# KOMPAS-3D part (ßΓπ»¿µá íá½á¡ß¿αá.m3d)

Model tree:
1. Эскиз:1
2. Операция выдавливания:1
     Расстояние 1 = 12
3. Эскиз:2
4. Вырезать элемент выдавливания:1
     Расстояние 1 = 4
5. Эскиз:3
6. Отверстие:1
7. Эскиз:4
8. Отверстие:2
9. Эскиз:5
10. Вырезать элемент выдавливания:2
     Расстояние 1 = 1
11. Скругление:1
     Радиус = 0.1
12. Скругление:2
     Радиус = 0.1
13. Скругление:3
     Радиус = 0.1
14. Скругление:4
     Радиус = 1
15. Скругление:5
     Радиус = 0.1

Referenced files in C:\Program Files\ASCON\KOMPAS-3D V13 Home\Sys\: holelib.lfr
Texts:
  Сплав АЛ8  ГОСТ 1583-93
  Отверстие 01
  (вариант 1)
